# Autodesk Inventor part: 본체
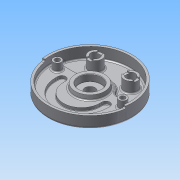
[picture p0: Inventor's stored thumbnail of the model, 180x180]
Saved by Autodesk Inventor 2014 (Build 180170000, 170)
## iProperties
Created: 2015-06
Part Number: 본체
Material: 알루미늄 6061
Document SubType Name: Modeling
Designer: Administrator
Density: 2.71 g/cm^3
Appearance: 알루미늄 - 평지
Mass: 1070.9 g
Surface Area: 1043.54 cm^2
Volume: 395.165 cm^3
Author: Administrator
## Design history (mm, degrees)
sketch "스케치1"
  geometry: C1 r 95 at (0, 0); 1 further point
  constraints: 1 centre point, 1 coincident
  dimensions: "d0" = 190 diameter of C1
extrude "돌출1" new body sketch "스케치1" distance "d1" = 32; taper "d2" = 0 deg
sketch "스케치2"
  geometry: C1 r 95 at (0, 0) reference; C2 r 90 at (0, 0)
  constraints: 1 centre point, 1 coincident
  dimensions: "d3" = 180 diameter of C2
extrude "돌출2" cut sketch "스케치2" distance "d4" = 18; taper "d5" = 0 deg
sketch "스케치3"
  geometry: C1 r 90 at (0, 0) reference; C2 r 35 at (0, 0)
  constraints: 1 centre point, 1 coincident
  dimensions: "d6" = 70 diameter of C2
extrude "돌출3" join sketch "스케치3" distance "d7" = 10; taper "d8" = -10 deg
sketch "스케치4"
  geometry: C1 r 95 at (0, 0) reference; C2 r 26 at (0, 0)
  constraints: 1 centre point, 1 coincident
  dimensions: "d9" = 52 diameter of C2
extrude "돌출4" join sketch "스케치4" distance "d10" = 12; taper "d11" = -15 deg
sketch "스케치5"
  geometry: L1 (-88.566, 16)-(88.566, 16); C1 r 35 at (0, 0) reference; A1 r 90 centre (0, 0) between (-88.566, 16) and (88.566, 16) reference; A2 r 42 centre (0, 0) between (38.833, 16) and (-38.833, 16); A3 r 90 centre (0, 0) between (88.566, 16) and (-88.566, 16)
  constraints: 6 point on circle, 2 centre point, 2 concentric, 2 end point, 2 point on line, 1 coincident, 1 horizontal
  dimensions: "d12" = 84 diameter of A2; "d13" = 16 distance from line of C1.centre L1
extrude "돌출5" cut sketch "스케치5" distance "d14" = 7; taper "d15" = 0 deg
fillet "모깎기1" dims "d16" = 10
sketch "스케치6"
  geometry: C1 r 15 at (-40, 52); C2 r 15 at (40, 52); A1 r 90 centre (0, 0) between (85.114, 29.25) and (-85.114, 29.25) reference
  constraints: 2 centre point, 1 equal radius
  dimensions: "d17" = 30 diameter of C1; "d18" = 52 vertical distance of A1.centre C1.centre; "d19" = 52 vertical distance of A1.centre C2.centre; "d20" = 80 distance of C2.centre C1.centre; "d21" = 40 horizontal distance of A1.centre C1.centre
extrude "돌출6" join sketch "스케치6" distance "d22" = 25; taper "d23" = 0 deg
hole "구멍1" diameter "d26" = 20; stored, may be unused: countersink angle "d30" = 90 deg, drill point angle "d32" = 118 deg; dims "d24" = 10, "d25" = 10, "d27" = 6, "d28" = 4, "d29" = 2, "d31" = 8
hole "구멍2" diameter "d35" = 20; stored, may be unused: countersink angle "d39" = 90 deg, drill point angle "d41" = 118 deg; dims "d33" = 10, "d34" = 10, "d36" = 6, "d37" = 4, "d38" = 2, "d40" = 8
sketch "스케치8"
  geometry: L1 (-6, 20.083)-(6, 20.083); L2 (6, 20.083)-(6, -20.083); L3 (6, -20.083)-(-6, -20.083); L4 (-6, -20.083)-(-6, 20.083); L5 (-6, 20.083)-(6, -20.083); L6 (6, 20.083)-(-6, -20.083); L7 (56.142, 6)-(103.858, 6); L8 (103.858, 6)-(103.858, -6); L9 (103.858, -6)-(56.142, -6); L10 (56.142, -6)-(56.142, 6); L11 (56.142, 6)-(103.858, -6); L12 (103.858, 6)-(56.142, -6); C1 r 15 at (0, 0) reference; C2 r 15 at (80, 0) reference; 1 further point
  constraints: 24 end point, 4 midpoint, 4 parallel, 2 horizontal, 2 perpendicular
  dimensions: "d42" = 12 distance of L1.start L1.end; "d43" = 12 distance of L7.end L8.end; "d44" = 40.16666 distance of L1.end L2.end; "d45" = 47.71654 distance of L7.start L7.end
extrude "돌출7" cut sketch "스케치8" distance "d46" = 3; taper "d47" = 0 deg
hole "구멍3" diameter "d50" = 23; stored, may be unused: countersink angle "d54" = 90 deg, drill point angle "d56" = 118 deg; dims "d48" = 10, "d49" = 10, "d51" = 6, "d52" = 50, "d53" = 15, "d55" = 8
sketch "스케치9"
  geometry: L1 (75.657, 16)-(45.033, 16) reference; L2 (-90, 0)-(90, 0); L3 (-90, -19)-(90, -19); L4 (-90, -14)-(90, -14); L5 (0, 0)-(0, -90); L6 (-59, -19)-(-59, -14); L7 (-41, -19)-(-41, -14); L8 (41, -19)-(41, -14); L9 (59, -19)-(59, -14); C1 r 35 at (0, 0) reference; A1 r 90 centre (0, 0) between (-85.114, 29.25) and (85.114, 29.25) reference; A2 r 41 centre (0, -19) between (-41, -19) and (41, -19); A3 r 59 centre (0, -19) between (-59, -19) and (59, -19); A4 r 9 centre (-50, -14) between (-41, -14) and (-59, -14); A5 r 9 centre (50, -14) between (59, -14) and (41, -14)
  constraints: 16 end point, 11 point on circle, 9 point on line, 8 tangent, 4 centre point, 4 perpendicular, 3 parallel, 1 coincident, 1 midpoint
  dimensions: "d57" = 180 distance of L2.start L2.end; "d58" = 19 distance between parallel lines of L3 L2; "d59" = 5 distance between parallel lines of L3 L4; "d62" = 59 radius of A3; "d63" = 41 radius of A2
extrude "돌출8" cut sketch "스케치9" distance "d64" = 7; taper "d65" = 0 deg
sketch "스케치10"
  geometry: L1 (-95, 0)-(90, 0); L2 (-89.124, -12.526)-(-94.075, -13.221); L3 (89.124, -12.526)-(94.075, -13.221); A1 r 90 centre (0, 0) between (90, 0) and (89.124, -12.526) reference; A2 r 95 centre (0, 0) between (-95, 0) and (-94.075, -13.221) reference; A3 r 90 centre (0, 0) between (-89.124, -12.526) and (89.124, -12.526); A4 r 95 centre (0, 0) between (-94.075, -13.221) and (94.075, -13.221)
  constraints: 10 point on circle, 6 end point, 2 centre point, 2 concentric, 1 horizontal
  dimensions: "d66" = 185 distance of L1.start L1.end; "d67" = 8 deg angle of L2 L1; "d68" = 8 deg angle of L3 L1; "d69" = 0 distance from line of A2.centre L3; "d70" = 0 distance from line of A2.centre L2
extrude "돌출9" cut sketch "스케치10" distance "d71" = 5; taper "d72" = 0 deg
sketch "스케치11"
  geometry: C1 r 35 at (0, 0) reference; C2 r 9 at (-74, 0); C3 r 9 at (74, 0); A1 r 90 centre (0, 0) between (-85.114, 29.25) and (85.114, 29.25) reference; A2 r 74 centre (0, 0) between (-74, 0) and (74, 0)
  constraints: 3 centre point, 2 horizontal alignment, 2 point on circle, 1 coincident
  dimensions: "d73" = 148 diameter of A2; "d74" = 18 diameter of C2; "d75" = 18 diameter of C3
extrude "돌출10" join sketch "스케치11" distance "d76" = 18; taper "d77" = 0 deg
sketch "스케치12"
  geometry: C1 r 9 at (74, 0) reference; C2 r 9 at (-74, 0) reference; 2 further points
  constraints: 2 coincident
hole "구멍4" sketch "스케치12" at (-74, 0), (74, 0) diameter "d78" = 11; stored, may be unused: countersink angle "d82" = 90 deg, drill point angle "d84" = 118 deg; dims "d79" = 6, "d80" = 18, "d81" = 11, "d83" = 8
sketch "스케치13"
  geometry: C1 r 95 at (0, 0) reference; C2 r 68 at (0, 0)
  constraints: 1 centre point, 1 coincident, 1 other
  dimensions: "d85" = 136 diameter of C2
feature "엠보싱1" sketch "스케치13" dims "d10" = 12, "d86" = 0.5, "d87" = 0
fillet "모깎기2" dims "d88" = 3
fillet "모깎기3" dims "d89" = 3
fillet "모깎기4" dims "d90" = 5
fillet "모깎기5" dims "d91" = 3
fillet "모깎기6" dims "d92" = 0.3
chamfer "모따기1" distance "d93" = 1; stored, may be unused: second distance "d94" = 2, angle "d95" = 45 deg
fillet "모깎기7" dims "d96" = 3
fillet "모깎기8" dims "d97" = 3
fillet "모깎기9" dims "d98" = 1
fillet "모깎기10" dims "d99" = 3
fillet "모깎기11" dims "d100" = 3
fillet "모깎기12" dims "d101" = 3
node "솔리드1"
other parameters: "d60" = 82, "d61" = 118
